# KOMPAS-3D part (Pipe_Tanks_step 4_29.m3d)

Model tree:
1. X Axis
2. Y Axis
3. Z Axis
     Òîëùèíà ñòåíêè 1 = 1

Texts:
  Pipe Dn 20
  Steel ASTM A295
  Three Point Plane
  Plane at Angle
  Line and Point Plane
  Axis through Two Vertices
  Axis of Feature
  Axis of Conical Surface
  Axis through Edge
  Trim by Surface
  Trim by Sketch
  Feature with No History
  Intersection Axis of Two Planes
  Two Line Plane
  Line and Face Plane
  Bend by line
  Hole in sheet body
  Cut in sheet body
  Point in CM
  Linear Dimension from Line to Point
  Surface Finish Symbol
  Geometric Tolerance Symbol
  Leader #1
  Leader #2
  Leader #3
  Shape Deviations and Datum
  Node point number
  Mark of coordination axis
  Node point designation
  Mark/Reference designation with leader
  Mark/reference designation on line
  Mark/Reference designation without leader
  Plane of section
